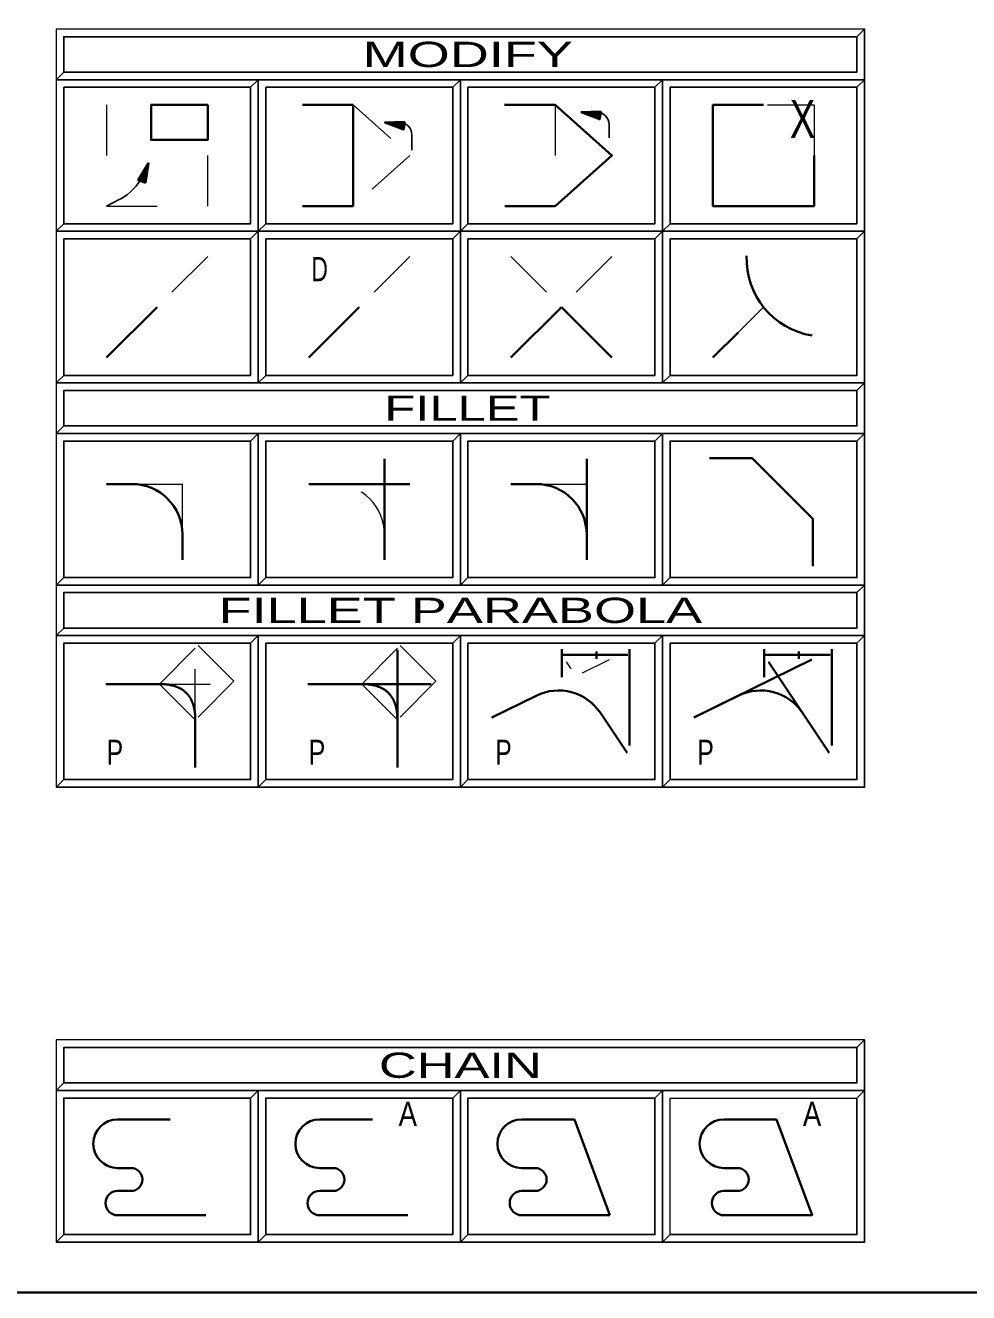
# Model space of a CAD drawing. Extents: x 95906.8 to 95923.6, y 90964.8 to 90972.8.
# Drawn here: x 95908.871 to 95910.738, y 90964.762 to 90967.269 of the extents above; entities that cross this region are included whole.
import ezdxf
from ezdxf.enums import TextEntityAlignment as Align

# ---------------------------------------------------------------- set-up
doc = ezdxf.new("R2010")
doc.units = 0
doc.header["$LTSCALE"] = 0.019
doc.linetypes.add('DOTTED', pattern=[1.5, 0.3, -1.2])
doc.linetypes.add('MEDIUM_DASHED', pattern=[4.5, 3, -1.5])
for name, color, linetype, lineweight in [('11', 7, 'Continuous', 25), ('12', 7, 'Continuous', 25), ('18', 7, 'Continuous', 25), ('2', 7, 'Continuous', 13), ('3', 7, 'Continuous', 25), ('6', 7, 'Continuous', 25), ('7', 7, 'Continuous', 35)]:
    doc.layers.add(name, color=color, linetype=linetype, lineweight=lineweight)

msp = doc.modelspace()

# ---------------------------------------------------------------- linework, layer by layer
at = {"layer": '11'}
for points in [[(95909.3473, 90966.8767), (95909.7173, 90966.8767), (95909.7173, 90967.1467), (95909.3473, 90967.1467)], [(95909.7473, 90966.8767), (95910.1173, 90966.8767), (95910.1173, 90967.1467), (95909.7473, 90967.1467)], [(95910.1473, 90966.8767), (95910.5173, 90966.8767), (95910.5173, 90967.1467), (95910.1473, 90967.1467)], [(95909.3473, 90966.5767), (95909.7173, 90966.5767), (95909.7173, 90966.8467), (95909.3473, 90966.8467)], [(95909.7473, 90966.5767), (95910.1173, 90966.5767), (95910.1173, 90966.8467), (95909.7473, 90966.8467)], [(95910.1473, 90966.5767), (95910.5173, 90966.5767), (95910.5173, 90966.8467), (95910.1473, 90966.8467)], [(95909.3473, 90966.1767), (95909.7173, 90966.1767), (95909.7173, 90966.4467), (95909.3473, 90966.4467)], [(95909.7473, 90966.1767), (95910.1173, 90966.1767), (95910.1173, 90966.4467), (95909.7473, 90966.4467)], [(95910.1473, 90966.1767), (95910.5173, 90966.1767), (95910.5173, 90966.4467), (95910.1473, 90966.4467)], [(95908.9473, 90965.7767), (95909.3173, 90965.7767), (95909.3173, 90966.0467), (95908.9473, 90966.0467)], [(95909.3473, 90965.7767), (95909.7173, 90965.7767), (95909.7173, 90966.0467), (95909.3473, 90966.0467)], [(95909.7473, 90965.7767), (95910.1173, 90965.7767), (95910.1173, 90966.0467), (95909.7473, 90966.0467)], [(95910.1473, 90965.7767), (95910.5173, 90965.7767), (95910.5173, 90966.0467), (95910.1473, 90966.0467)], [(95909.3473, 90964.8767), (95909.7173, 90964.8767), (95909.7173, 90965.1467), (95909.3473, 90965.1467)], [(95909.7473, 90964.8767), (95910.1173, 90964.8767), (95910.1173, 90965.1467), (95909.7473, 90965.1467)]]:
    msp.add_lwpolyline(points, close=True, dxfattribs=at)
at = {"layer": '12'}
for points in [[(95908.9473, 90966.8767), (95909.3173, 90966.8767), (95909.3173, 90967.1467), (95908.9473, 90967.1467)], [(95908.9473, 90966.5767), (95909.3173, 90966.5767), (95909.3173, 90966.8467), (95908.9473, 90966.8467)], [(95908.9473, 90966.1767), (95909.3173, 90966.1767), (95909.3173, 90966.4467), (95908.9473, 90966.4467)], [(95908.9473, 90964.8767), (95909.3173, 90964.8767), (95909.3173, 90965.1467), (95908.9473, 90965.1467)]]:
    msp.add_lwpolyline(points, close=True, dxfattribs=at)
at = {"layer": '18'}
for points in [[(95908.9473, 90967.1767), (95910.5173, 90967.1767), (95910.5173, 90967.2467), (95908.9473, 90967.2467)], [(95908.9473, 90966.4767), (95910.5173, 90966.4767), (95910.5173, 90966.5467), (95908.9473, 90966.5467)], [(95908.9473, 90966.0767), (95910.5173, 90966.0767), (95910.5173, 90966.1467), (95908.9473, 90966.1467)], [(95908.9473, 90965.1767), (95910.5173, 90965.1767), (95910.5173, 90965.2467), (95908.9473, 90965.2467)]]:
    msp.add_lwpolyline(points, close=True, dxfattribs=at)
at = {"layer": '2'}
for points in [[(95908.9323, 90967.2617), (95908.9323, 90967.1617), (95908.9473, 90967.1767), (95908.9473, 90967.2467), (95910.5173, 90967.2467), (95910.5323, 90967.2617)], [(95908.9323, 90967.1617), (95908.9323, 90966.8617), (95908.9473, 90966.8767), (95908.9473, 90967.1467), (95909.3173, 90967.1467), (95909.3323, 90967.1617)], [(95909.3323, 90967.1617), (95909.3323, 90966.8617), (95909.3473, 90966.8767), (95909.3473, 90967.1467), (95909.7173, 90967.1467), (95909.7323, 90967.1617)], [(95909.7323, 90967.1617), (95909.7323, 90966.8617), (95909.7473, 90966.8767), (95909.7473, 90967.1467), (95910.1173, 90967.1467), (95910.1323, 90967.1617)], [(95910.1323, 90967.1617), (95910.1323, 90966.8617), (95910.1473, 90966.8767), (95910.1473, 90967.1467), (95910.5173, 90967.1467), (95910.5323, 90967.1617)], [(95908.9323, 90966.8617), (95908.9323, 90966.5617), (95908.9473, 90966.5767), (95908.9473, 90966.8467), (95909.3173, 90966.8467), (95909.3323, 90966.8617)], [(95909.3323, 90966.8617), (95909.3323, 90966.5617), (95909.3473, 90966.5767), (95909.3473, 90966.8467), (95909.7173, 90966.8467), (95909.7323, 90966.8617)], [(95909.7323, 90966.8617), (95909.7323, 90966.5617), (95909.7473, 90966.5767), (95909.7473, 90966.8467), (95910.1173, 90966.8467), (95910.1323, 90966.8617)], [(95910.1323, 90966.8617), (95910.1323, 90966.5617), (95910.1473, 90966.5767), (95910.1473, 90966.8467), (95910.5173, 90966.8467), (95910.5323, 90966.8617)], [(95908.9323, 90966.5617), (95908.9323, 90966.4617), (95908.9473, 90966.4767), (95908.9473, 90966.5467), (95910.5173, 90966.5467), (95910.5323, 90966.5617)], [(95908.9323, 90966.4617), (95908.9323, 90966.1617), (95908.9473, 90966.1767), (95908.9473, 90966.4467), (95909.3173, 90966.4467), (95909.3323, 90966.4617)], [(95909.3323, 90966.4617), (95909.3323, 90966.1617), (95909.3473, 90966.1767), (95909.3473, 90966.4467), (95909.7173, 90966.4467), (95909.7323, 90966.4617)], [(95909.7323, 90966.4617), (95909.7323, 90966.1617), (95909.7473, 90966.1767), (95909.7473, 90966.4467), (95910.1173, 90966.4467), (95910.1323, 90966.4617)], [(95910.1323, 90966.4617), (95910.1323, 90966.1617), (95910.1473, 90966.1767), (95910.1473, 90966.4467), (95910.5173, 90966.4467), (95910.5323, 90966.4617)], [(95908.9323, 90966.1617), (95908.9323, 90966.0617), (95908.9473, 90966.0767), (95908.9473, 90966.1467), (95910.5173, 90966.1467), (95910.5323, 90966.1617)], [(95908.9323, 90966.0617), (95908.9323, 90965.7617), (95908.9473, 90965.7767), (95908.9473, 90966.0467), (95909.3173, 90966.0467), (95909.3323, 90966.0617)], [(95909.3323, 90966.0617), (95909.3323, 90965.7617), (95909.3473, 90965.7767), (95909.3473, 90966.0467), (95909.7173, 90966.0467), (95909.7323, 90966.0617)], [(95909.7323, 90966.0617), (95909.7323, 90965.7617), (95909.7473, 90965.7767), (95909.7473, 90966.0467), (95910.1173, 90966.0467), (95910.1323, 90966.0617)], [(95910.1323, 90966.0617), (95910.1323, 90965.7617), (95910.1473, 90965.7767), (95910.1473, 90966.0467), (95910.5173, 90966.0467), (95910.5323, 90966.0617)], [(95908.9323, 90965.2617), (95908.9323, 90965.1617), (95908.9473, 90965.1767), (95908.9473, 90965.2467), (95910.5173, 90965.2467), (95910.5323, 90965.2617)], [(95908.9323, 90965.1617), (95908.9323, 90964.8617), (95908.9473, 90964.8767), (95908.9473, 90965.1467), (95909.3173, 90965.1467), (95909.3323, 90965.1617)], [(95909.3323, 90965.1617), (95909.3323, 90964.8617), (95909.3473, 90964.8767), (95909.3473, 90965.1467), (95909.7173, 90965.1467), (95909.7323, 90965.1617)], [(95909.7323, 90965.1617), (95909.7323, 90964.8617), (95909.7473, 90964.8767), (95909.7473, 90965.1467), (95910.1173, 90965.1467), (95910.1323, 90965.1617)], [(95910.1323, 90965.1617), (95910.1323, 90964.8617), (95910.1473, 90964.8767), (95910.1473, 90965.1467), (95910.5173, 90965.1467), (95910.5323, 90965.1617)]]:
    msp.add_lwpolyline(points, close=True, dxfattribs=at)
at = {"layer": '3'}
for points in [[(95908.9323, 90967.1617), (95910.5323, 90967.1617), (95910.5323, 90967.2617), (95910.5173, 90967.2467), (95910.5173, 90967.1767), (95908.9473, 90967.1767)], [(95908.9323, 90966.8617), (95909.3323, 90966.8617), (95909.3323, 90967.1617), (95909.3173, 90967.1467), (95909.3173, 90966.8767), (95908.9473, 90966.8767)], [(95909.3323, 90966.8617), (95909.7323, 90966.8617), (95909.7323, 90967.1617), (95909.7173, 90967.1467), (95909.7173, 90966.8767), (95909.3473, 90966.8767)], [(95909.7323, 90966.8617), (95910.1323, 90966.8617), (95910.1323, 90967.1617), (95910.1173, 90967.1467), (95910.1173, 90966.8767), (95909.7473, 90966.8767)], [(95910.1323, 90966.8617), (95910.5323, 90966.8617), (95910.5323, 90967.1617), (95910.5173, 90967.1467), (95910.5173, 90966.8767), (95910.1473, 90966.8767)], [(95908.9323, 90966.5617), (95909.3323, 90966.5617), (95909.3323, 90966.8617), (95909.3173, 90966.8467), (95909.3173, 90966.5767), (95908.9473, 90966.5767)], [(95909.3323, 90966.5617), (95909.7323, 90966.5617), (95909.7323, 90966.8617), (95909.7173, 90966.8467), (95909.7173, 90966.5767), (95909.3473, 90966.5767)], [(95909.7323, 90966.5617), (95910.1323, 90966.5617), (95910.1323, 90966.8617), (95910.1173, 90966.8467), (95910.1173, 90966.5767), (95909.7473, 90966.5767)], [(95910.1323, 90966.5617), (95910.5323, 90966.5617), (95910.5323, 90966.8617), (95910.5173, 90966.8467), (95910.5173, 90966.5767), (95910.1473, 90966.5767)], [(95908.9323, 90966.4617), (95910.5323, 90966.4617), (95910.5323, 90966.5617), (95910.5173, 90966.5467), (95910.5173, 90966.4767), (95908.9473, 90966.4767)], [(95908.9323, 90966.1617), (95909.3323, 90966.1617), (95909.3323, 90966.4617), (95909.3173, 90966.4467), (95909.3173, 90966.1767), (95908.9473, 90966.1767)], [(95909.3323, 90966.1617), (95909.7323, 90966.1617), (95909.7323, 90966.4617), (95909.7173, 90966.4467), (95909.7173, 90966.1767), (95909.3473, 90966.1767)], [(95909.7323, 90966.1617), (95910.1323, 90966.1617), (95910.1323, 90966.4617), (95910.1173, 90966.4467), (95910.1173, 90966.1767), (95909.7473, 90966.1767)], [(95910.1323, 90966.1617), (95910.5323, 90966.1617), (95910.5323, 90966.4617), (95910.5173, 90966.4467), (95910.5173, 90966.1767), (95910.1473, 90966.1767)], [(95908.9323, 90966.0617), (95910.5323, 90966.0617), (95910.5323, 90966.1617), (95910.5173, 90966.1467), (95910.5173, 90966.0767), (95908.9473, 90966.0767)], [(95908.9323, 90965.7617), (95909.3323, 90965.7617), (95909.3323, 90966.0617), (95909.3173, 90966.0467), (95909.3173, 90965.7767), (95908.9473, 90965.7767)], [(95909.3323, 90965.7617), (95909.7323, 90965.7617), (95909.7323, 90966.0617), (95909.7173, 90966.0467), (95909.7173, 90965.7767), (95909.3473, 90965.7767)], [(95909.7323, 90965.7617), (95910.1323, 90965.7617), (95910.1323, 90966.0617), (95910.1173, 90966.0467), (95910.1173, 90965.7767), (95909.7473, 90965.7767)], [(95910.1323, 90965.7617), (95910.5323, 90965.7617), (95910.5323, 90966.0617), (95910.5173, 90966.0467), (95910.5173, 90965.7767), (95910.1473, 90965.7767)], [(95908.9323, 90965.1617), (95910.5323, 90965.1617), (95910.5323, 90965.2617), (95910.5173, 90965.2467), (95910.5173, 90965.1767), (95908.9473, 90965.1767)], [(95908.9323, 90964.8617), (95909.3323, 90964.8617), (95909.3323, 90965.1617), (95909.3173, 90965.1467), (95909.3173, 90964.8767), (95908.9473, 90964.8767)], [(95909.3323, 90964.8617), (95909.7323, 90964.8617), (95909.7323, 90965.1617), (95909.7173, 90965.1467), (95909.7173, 90964.8767), (95909.3473, 90964.8767)], [(95909.7323, 90964.8617), (95910.1323, 90964.8617), (95910.1323, 90965.1617), (95910.1173, 90965.1467), (95910.1173, 90964.8767), (95909.7473, 90964.8767)], [(95910.1323, 90964.8617), (95910.5323, 90964.8617), (95910.5323, 90965.1617), (95910.5173, 90965.1467), (95910.5173, 90964.8767), (95910.1473, 90964.8767)]]:
    msp.add_lwpolyline(points, close=True, dxfattribs=at)
at = {"layer": '6', "linetype": 'MEDIUM_DASHED', "lineweight": 13}
for p, q in [((95909.9201, 90967.1117), (95909.9201, 90966.9117)), ((95909.2323, 90966.8117), (95909.1323, 90966.7117)), ((95909.6323, 90966.8117), (95909.5323, 90966.7117)), ((95909.8323, 90966.8117), (95909.9323, 90966.7117)), ((95910.0323, 90966.8117), (95909.9323, 90966.7117)), ((95910.3323, 90966.7117), (95910.2823, 90966.6617)), ((95909.1823, 90966.2617), (95909.1823, 90966.4117)), ((95909.0823, 90966.3617), (95909.2323, 90966.3617)), ((95909.8823, 90966.3617), (95910.0323, 90966.3617))]:
    msp.add_line(p, q, dxfattribs=at)
at = {"layer": '6'}
for p, q in [((95909.9714, 90967.0976), (95910.0018, 90967.0976)), ((95909.6113, 90967.0776), (95909.5825, 90967.0776)), ((95910.0268, 90967.0726), (95910.0268, 90967.0469)), ((95909.6363, 90967.0223), (95909.6363, 90967.0526)), ((95909.1036, 90966.9717), (95909.1152, 90966.9962)), ((95909.0323, 90966.9117), (95909.0587, 90966.9252))]:
    msp.add_line(p, q, dxfattribs=at)
at = {"layer": '6', "lineweight": 35}
for p, q in [((95910.0093, 90967.091), (95909.9715, 90967.0977)), ((95909.9715, 90967.0977), (95910.0099, 90967.0946)), ((95909.6208, 90967.0705), (95909.583, 90967.0772)), ((95909.583, 90967.0772), (95909.6214, 90967.074)), ((95909.1021, 90966.9601), (95909.1152, 90966.9962)), ((95909.1152, 90966.9962), (95909.1054, 90966.9589)), ((95909.0323, 90966.6117), (95909.1323, 90966.7117)), ((95909.4323, 90966.6117), (95909.5323, 90966.7117)), ((95909.8323, 90966.6117), (95909.9323, 90966.7117)), ((95910.0323, 90966.6117), (95909.9323, 90966.7117)), ((95910.2323, 90966.6117), (95910.2823, 90966.6617)), ((95909.5823, 90966.2117), (95909.5823, 90966.4117)), ((95909.9823, 90966.2617), (95909.9823, 90966.4117)), ((95909.0323, 90966.3617), (95909.0823, 90966.3617)), ((95909.4323, 90966.3617), (95909.6323, 90966.3617)), ((95909.8323, 90966.3617), (95909.8823, 90966.3617)), ((95909.1823, 90966.2117), (95909.1823, 90966.2617)), ((95909.9823, 90966.2117), (95909.9823, 90966.2617)), ((95909.6077, 90965.8952), (95909.6077, 90966.0335)), ((95909.9334, 90965.9796), (95909.9334, 90966.0351)), ((95910.0672, 90965.8441), (95910.0672, 90966.0351)), ((95910.3334, 90965.9796), (95910.3334, 90966.0351)), ((95910.4672, 90965.8441), (95910.4672, 90966.0351)), ((95909.9317, 90966.0237), (95910.064, 90966.0237)), ((95910.0019, 90966.0155), (95910.0019, 90966.0302)), ((95910.1946, 90965.8996), (95910.4278, 90966.0147)), ((95910.3317, 90966.0237), (95910.464, 90966.0237)), ((95910.4623, 90965.8295), (95910.3422, 90966.01)), ((95910.4019, 90966.0155), (95910.4019, 90966.0302)), ((95909.0306, 90965.9659), (95909.137, 90965.9659)), ((95909.4306, 90965.9659), (95909.537, 90965.9659)), ((95909.537, 90965.9659), (95909.6746, 90965.9659)), ((95909.7946, 90965.8996), (95909.8821, 90965.9428)), ((95910.1946, 90965.8996), (95910.2821, 90965.9428)), ((95910.0623, 90965.8295), (95910.0096, 90965.9087)), ((95910.4623, 90965.8295), (95910.4096, 90965.9087)), ((95909.2077, 90965.801), (95909.2077, 90965.8952)), ((95909.6077, 90965.801), (95909.6077, 90965.8952)), ((95909.1582, 90965.1045), (95909.054, 90965.1045)), ((95909.5582, 90965.1045), (95909.454, 90965.1045)), ((95909.9582, 90965.1045), (95909.854, 90965.1045)), ((95909.9582, 90965.1045), (95910.0283, 90964.9148)), ((95910.3582, 90965.1045), (95910.254, 90965.1045)), ((95909.054, 90965.0081), (95909.0804, 90965.0081)), ((95909.454, 90965.0081), (95909.4804, 90965.0081)), ((95909.854, 90965.0081), (95909.8804, 90965.0081)), ((95910.254, 90965.0081), (95910.2804, 90965.0081)), ((95909.0804, 90964.963), (95909.054, 90964.963)), ((95909.4804, 90964.963), (95909.454, 90964.963)), ((95909.8804, 90964.963), (95909.854, 90964.963)), ((95910.2804, 90964.963), (95910.254, 90964.963)), ((95909.054, 90964.9148), (95909.2283, 90964.9148)), ((95909.454, 90964.9148), (95909.6283, 90964.9148)), ((95909.854, 90964.9148), (95910.0283, 90964.9148))]:
    msp.add_line(p, q, dxfattribs=at)
at = {"layer": '6', "linetype": 'DOTTED', "lineweight": 13}
for p, q in [((95909.2077, 90965.8952), (95909.2077, 90966.0335)), ((95909.7946, 90965.8996), (95910.0278, 90966.0147)), ((95910.0623, 90965.8295), (95909.9422, 90966.01)), ((95909.137, 90965.9659), (95909.2746, 90965.9659))]:
    msp.add_line(p, q, dxfattribs=at)
at = {"layer": '6', "linetype": 'MEDIUM_DASHED', "lineweight": 13}
msp.add_lwpolyline([(95909.2323, 90967.1117), (95909.0323, 90967.1117), (95909.0323, 90966.9117), (95909.2323, 90966.9117)], close=True, dxfattribs=at)
at = {"layer": '6', "lineweight": 35}
msp.add_lwpolyline([(95909.2323, 90967.1117), (95909.1201, 90967.1117), (95909.1201, 90967.0425), (95909.2323, 90967.0425)], close=True, dxfattribs=at)
for points in [[(95909.42, 90967.1117), (95909.5201, 90967.1117), (95909.5201, 90966.9117), (95909.4202, 90966.9117)], [(95909.82, 90967.1117), (95909.9201, 90967.1117), (95910.0323, 90967.0117), (95909.9201, 90966.9117), (95909.8202, 90966.9117)], [(95910.3324, 90967.1117), (95910.2323, 90967.1117), (95910.2323, 90966.9117), (95910.4323, 90966.9117), (95910.4323, 90967.0117)], [(95910.0107, 90967.0986), (95910.008, 90967.0835), (95909.9715, 90967.0977)], [(95910.0107, 90967.0986), (95909.9715, 90967.0977), (95910.0087, 90967.0873)], [(95909.6221, 90967.0781), (95909.6195, 90967.0629), (95909.583, 90967.0772)], [(95909.6221, 90967.0781), (95909.583, 90967.0772), (95909.6201, 90967.0667)], [(95909.1093, 90966.9575), (95909.0948, 90966.9627), (95909.1152, 90966.9962)], [(95909.1093, 90966.9575), (95909.1152, 90966.9962), (95909.0985, 90966.9614)], [(95910.2257, 90966.4131), (95910.3096, 90966.4131), (95910.4296, 90966.2931), (95910.4296, 90966.1992)], [(95910.254, 90964.9148), (95910.4283, 90964.9148), (95910.3582, 90965.1045)]]:
    msp.add_lwpolyline(points, dxfattribs=at)
at = {"layer": '6', "linetype": 'MEDIUM_DASHED', "lineweight": 13}
for points in [[(95909.5201, 90967.1117), (95909.6323, 90967.0117), (95909.5201, 90966.9117)], [(95910.3405, 90967.1117), (95910.4323, 90967.1117), (95910.4323, 90967.0117)]]:
    msp.add_lwpolyline(points, dxfattribs=at)
at = {"layer": '6', "linetype": 'DOTTED', "lineweight": 13}
for points in [[(95909.2077, 90965.8952), (95909.137, 90965.9659), (95909.2131, 90966.042), (95909.2838, 90965.9713)], [(95909.6077, 90965.8952), (95909.537, 90965.9659), (95909.6131, 90966.042), (95909.6838, 90965.9713)]]:
    msp.add_lwpolyline(points, close=True, dxfattribs=at)
at = {"layer": '6'}
for centre, radius, start, end in [((95910.0018, 90967.0726), 0.025, 0, 90), ((95909.6113, 90967.0526), 0.025, 0, 90), ((95909.0131, 90967.0142), 0.1, 297.1547, 334.867)]:
    msp.add_arc(centre, radius, start, end, dxfattribs=at)
at = {"layer": '6', "lineweight": 35}
for centre, radius, start, end in [((95910.4531, 90966.8079), 0.1544, 178.1343, 260.7711), ((95909.0823, 90966.2617), 0.1, 0, 90), ((95909.8823, 90966.2617), 0.1, 0, 90), ((95909.9264, 90965.8532), 0.1, 33.7228, 116.3032), ((95910.3264, 90965.8532), 0.1, 33.7228, 116.3032), ((95909.054, 90965.0563), 0.0482, 90, 270), ((95909.454, 90965.0563), 0.0482, 90, 270), ((95909.854, 90965.0563), 0.0482, 90, 270), ((95910.254, 90965.0563), 0.0482, 90, 270), ((95909.0804, 90964.9856), 0.0226, 270, 90), ((95909.4804, 90964.9856), 0.0226, 270, 90), ((95909.8804, 90964.9856), 0.0226, 270, 90), ((95910.2804, 90964.9856), 0.0226, 270, 90), ((95909.054, 90964.9389), 0.0241, 90, 270), ((95909.454, 90964.9389), 0.0241, 90, 270), ((95909.854, 90964.9389), 0.0241, 90, 270), ((95910.254, 90964.9389), 0.0241, 90, 270)]:
    msp.add_arc(centre, radius, start, end, dxfattribs=at)
at = {"layer": '6', "linetype": 'MEDIUM_DASHED', "lineweight": 13}
msp.add_arc((95909.4823, 90966.2617), 0.1, 0, 90, dxfattribs=at)
at = {"layer": '6', "lineweight": 35}
for points in [[(95909.2077, 90965.8952), (95909.2077, 90965.8985), (95909.2075, 90965.9018), (95909.2073, 90965.9049), (95909.2071, 90965.908), (95909.2067, 90965.911), (95909.2063, 90965.9139), (95909.2057, 90965.9168), (95909.2051, 90965.9196), (95909.2045, 90965.9222), (95909.2037, 90965.9249), (95909.2028, 90965.9274), (95909.2019, 90965.9298), (95909.2009, 90965.9322), (95909.1998, 90965.9345), (95909.1987, 90965.9367), (95909.1974, 90965.9388), (95909.1961, 90965.9408), (95909.1947, 90965.9428), (95909.1932, 90965.9447), (95909.1917, 90965.9465), (95909.19, 90965.9482), (95909.1883, 90965.9499), (95909.1865, 90965.9514), (95909.1846, 90965.9529), (95909.1826, 90965.9543), (95909.1806, 90965.9556), (95909.1785, 90965.9569), (95909.1763, 90965.958), (95909.174, 90965.9591), (95909.1716, 90965.9601), (95909.1692, 90965.961), (95909.1667, 90965.9619), (95909.164, 90965.9627), (95909.1614, 90965.9633), (95909.1586, 90965.9639), (95909.1557, 90965.9645), (95909.1528, 90965.9649), (95909.1498, 90965.9653), (95909.1467, 90965.9655), (95909.1436, 90965.9657), (95909.1403, 90965.9659), (95909.137, 90965.9659)], [(95909.6077, 90965.8952), (95909.6077, 90965.8985), (95909.6075, 90965.9018), (95909.6073, 90965.9049), (95909.6071, 90965.908), (95909.6067, 90965.911), (95909.6063, 90965.9139), (95909.6057, 90965.9168), (95909.6051, 90965.9196), (95909.6045, 90965.9222), (95909.6037, 90965.9249), (95909.6028, 90965.9274), (95909.6019, 90965.9298), (95909.6009, 90965.9322), (95909.5998, 90965.9345), (95909.5987, 90965.9367), (95909.5974, 90965.9388), (95909.5961, 90965.9408), (95909.5947, 90965.9428), (95909.5932, 90965.9447), (95909.5917, 90965.9465), (95909.59, 90965.9482), (95909.5883, 90965.9499), (95909.5865, 90965.9514), (95909.5846, 90965.9529), (95909.5826, 90965.9543), (95909.5806, 90965.9556), (95909.5785, 90965.9569), (95909.5763, 90965.958), (95909.574, 90965.9591), (95909.5716, 90965.9601), (95909.5692, 90965.961), (95909.5667, 90965.9619), (95909.564, 90965.9627), (95909.5614, 90965.9633), (95909.5586, 90965.9639), (95909.5557, 90965.9645), (95909.5528, 90965.9649), (95909.5498, 90965.9653), (95909.5467, 90965.9655), (95909.5436, 90965.9657), (95909.5403, 90965.9659), (95909.537, 90965.9659)]]:
    msp.add_spline(points, degree=3, dxfattribs=at)
at = {"layer": '7'}
msp.add_lwpolyline([(95906.8323, 90972.7617), (95918.8323, 90972.7617), (95918.8323, 90964.7617), (95906.8323, 90964.7617)], close=True, dxfattribs=at)

# ---------------------------------------------------------------- texts
at = {"layer": '6'}
for s, height, width, p in [('X', 0.0752, 0.75, (95910.4095, 90967.0462)), ('D', 0.048, 0.7, (95909.4538, 90966.763)), ('P', 0.0491, 0.75, (95909.0486, 90965.8065)), ('P', 0.0491, 0.75, (95909.4486, 90965.8065)), ('P', 0.0491, 0.75, (95909.8176, 90965.8065)), ('P', 0.0491, 0.75, (95910.2176, 90965.8065)), ('A', 0.048, 0.85, (95909.6283, 90965.0914)), ('A', 0.048, 0.85, (95910.4284, 90965.0914))]:
    msp.add_text(s, height=height, dxfattribs=dict(at, width=width)).set_placement(p, align=Align.CENTER)
at = {"layer": '7'}
for s, width, p in [('         MODIFY        ', 1.6, (95909.7322, 90967.1867)), ('         FILLET        ', 1.5, (95909.7323, 90966.4867)), ('    FILLET PARABOLA    ', 1.6, (95909.7323, 90966.0867)), ('         CHAIN         ', 1.55, (95909.7323, 90965.1867))]:
    msp.add_text(s, height=0.04999, dxfattribs=dict(at, width=width)).set_placement(p, align=Align.CENTER)

doc.saveas('drawing.dxf')
